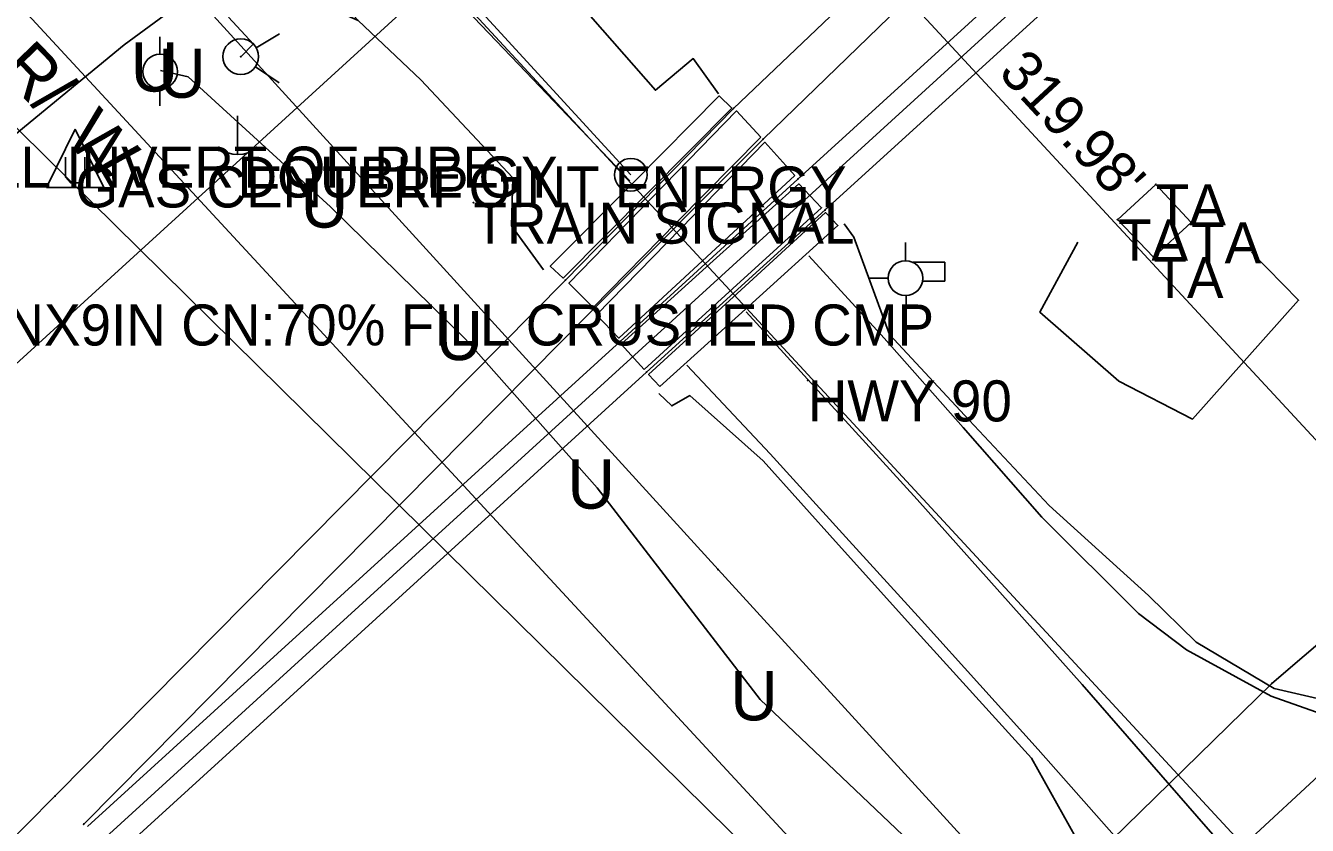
# Model space of a CAD drawing. Extents: x 1660112 to 1662239, y 668919 to 671377.
# Drawn here: x 1661444.4 to 1661600.6, y 669917.5 to 670014.9 of the extents above; entities that cross this region are included whole.
import ezdxf

# ---------------------------------------------------------------- set-up
doc = ezdxf.new("R2010")
doc.units = 0
for name, color, linetype in [('Default', 7, 'Continuous'), ('R_Annotation', 7, 'Continuous'), ('R_Horz Alg', 7, 'Continuous'), ('R_Horz Alg Annot', 7, 'Continuous'), ('S_BUILDING', 7, 'Continuous'), ('S_BUILDING_ANNOT', 7, 'Continuous'), ('S_EDGE_CONCRETE', 7, 'Continuous'), ('S_EDGE_PAVEMENT', 7, 'Continuous'), ('S_EXIST_ROW', 7, 'Continuous'), ('S_EXIST_ROW_ANNOT', 7, 'Continuous'), ('S_EXISTING_ALIGNMENT', 7, 'Continuous'), ('S_FIBER_OPTIC_CABLE', 7, 'Continuous'), ('S_MISC_STRUCTURES_ANNOT', 7, 'Continuous'), ('S_MSC_PT_SYM', 7, 'Continuous'), ('S_PAVEMENT_CROWN', 7, 'Continuous'), ('S_RAILROAD', 7, 'Continuous'), ('S_SANITARY_SEWER', 7, 'Continuous'), ('S_SHOULDER', 7, 'Continuous'), ('S_SIDE_DRAIN_ANNOT', 7, 'Continuous'), ('S_STR_PT_SYM', 7, 'Continuous'), ('S_SURVEY_TEXT_ANNOT', 7, 'Continuous'), ('S_UNDERGROUND_CABLE', 7, 'Continuous'), ('S_UTILITY_POLE', 7, 'Continuous'), ('S_UTILITY_POLE_ANNOT', 7, 'Continuous'), ('S_UTL_PT_SYM', 7, 'Continuous'), ('S_WATER_UTILITIES', 7, 'Continuous')]:
    doc.layers.add(name, color=color, linetype=linetype)

msp = doc.modelspace()

# ---------------------------------------------------------------- linework, layer by layer
at = {"layer": 'R_Horz Alg'}
msp.add_line((1661473.81, 670045.11), (1661518.2, 669996.77), dxfattribs=at)
at = {"layer": 'R_Horz Alg Annot'}
msp.add_circle((1661518.2, 669996.77), 2, dxfattribs=at)
at = {"layer": 'S_BUILDING'}
for p, q in [((1661582.19, 669995.6), (1661577.57, 669991.32)), ((1661586.47, 669990.97), (1661582.19, 669995.6)), ((1661577.5, 669991.3), (1661581.89, 669986.74)), ((1661581.89, 669986.74), (1661586.47, 669990.97))]:
    msp.add_line(p, q, dxfattribs=at)
at = {"layer": 'S_EDGE_CONCRETE'}
for points in [[(1661530.51, 670004.88), (1661528.97, 670006.37), (1661518.67, 669995.99), (1661508.37, 669985.62), (1661509.93, 669984.17), (1661520.22, 669994.53)], [(1661534.04, 670001.36), (1661523.82, 669990.98), (1661513.59, 669980.6), (1661510.64, 669983.54), (1661520.85, 669994.04), (1661531.07, 670004.54)], [(1661538.2, 669996.67), (1661527.46, 669986.77), (1661516.72, 669976.86), (1661514.03, 669979.7), (1661524.28, 669990.22), (1661534.53, 670000.74)], [(1661519.81, 669973.05), (1661517.01, 669976.14), (1661527.83, 669985.9), (1661538.65, 669995.66), (1661541.44, 669992.74), (1661530.63, 669982.89)], [(1661521.74, 669970.95), (1661520.36, 669972.41), (1661531.15, 669982.29), (1661541.93, 669992.16), (1661543.43, 669990.57), (1661532.58, 669980.76)]]:
    msp.add_lwpolyline(points, close=True, dxfattribs=at)
at = {"layer": 'S_EDGE_PAVEMENT'}
for points in [[(1661528.89, 670006.64), (1661525.81, 670010.93), (1661521.19, 670007.06), (1661512.12, 670017.42), (1661503.06, 670027.78), (1661494.14, 670038.45), (1661485.22, 670049.12), (1661475.65, 670058.13), (1661469.7, 670064.69), (1661453.26, 670082.63), (1661441.58, 670095.54), (1661429.9, 670108.45), (1661415.33, 670123.89), (1661400.76, 670139.32), (1661387.62, 670152.61), (1661374.47, 670165.9), (1661358.81, 670181.9), (1661343.14, 670197.9), (1661339.48, 670201.44), (1661329.75, 670211.05), (1661320.02, 670220.65), (1661304.77, 670236.19)], [(1661507.57, 669985.17), (1661503.63, 669990.55), (1661503.83, 669996.41), (1661492.59, 670008.33), (1661484.98, 670015.56), (1661475.91, 670025.37), (1661466.84, 670035.18), (1661454.4, 670049.73), (1661445.95, 670059), (1661437.51, 670068.28), (1661425.39, 670081.13), (1661413.28, 670093.99), (1661399.68, 670108.94), (1661386.08, 670123.89), (1661373.13, 670137.66), (1661360.18, 670151.43), (1661345.14, 670167.24), (1661330.11, 670183.04), (1661325.69, 670187.24), (1661316.74, 670196.41), (1661307.8, 670205.57), (1661291.28, 670222.16)], [(1661484.97, 670015.57), (1661481.44, 670017.1), (1661474.37, 670019.33), (1661466.03, 670019.66), (1661456.43, 670012.6), (1661444.31, 670002.59), (1661432.19, 669992.58), (1661429.76, 669993.52), (1661418.03, 669982.83), (1661399.88, 669965.82), (1661383.18, 669950.54), (1661366.48, 669935.26), (1661355.84, 669925.69), (1661345.19, 669916.12), (1661334.54, 669906.55), (1661323.9, 669896.98), (1661314.39, 669888.26), (1661304.88, 669879.54), (1661295.37, 669870.82), (1661285.87, 669862.1), (1661271.87, 669849.3), (1661257.87, 669836.51)], [(1661593.85, 669987.34), (1661599.58, 669981.47), (1661586.66, 669967), (1661577.69, 669971.61), (1661568.05, 669980.02), (1661572.66, 669988.57)], [(1661539.87, 669986.88), (1661549.09, 669976.87), (1661558.69, 669965.95), (1661568.29, 669955.03), (1661580.08, 669943.31), (1661585.93, 669938.89), (1661596.24, 669933.25), (1661605.77, 669929.84), (1661617.85, 669928.83), (1661635.53, 669933.18), (1661641.44, 669936.4), (1661650.28, 669942.7)], [(1661432.01, 669741.93), (1661449.2, 669757.82), (1661461.17, 669768.88), (1661473.15, 669779.94), (1661485.12, 669791), (1661497.09, 669802.06), (1661512.08, 669815.85), (1661527.07, 669829.65), (1661544.05, 669845.51), (1661561.04, 669861.38), (1661565.83, 669865.41), (1661573.24, 669872.37), (1661579.19, 669880.3), (1661583.76, 669891.47), (1661584.04, 669901.2), (1661578.64, 669914.49), (1661567.83, 669926.75), (1661553.64, 669942.48), (1661544.41, 669952.61), (1661535.19, 669962.75), (1661525.02, 669973.56)]]:
    msp.add_lwpolyline(points, dxfattribs=at)
at = {"layer": 'S_EXIST_ROW'}
for p, q in [((1661266.05, 669812.17), (1661715.82, 670222.22)), ((1661622.22, 669942.24), (1661404.92, 670177.11)), ((1661563.48, 669887.93), (1661347.41, 670121.48)), ((1661563.48, 669887.93), (1661622.22, 669942.24))]:
    msp.add_line(p, q, dxfattribs=at)
at = {"layer": 'S_EXISTING_ALIGNMENT'}
for p, q in [((1661299.73, 669775.22), (1661749.51, 670185.28)), ((1661613.41, 669892.86), (1661376.17, 670149.3))]:
    msp.add_line(p, q, dxfattribs=at)
at = {"layer": 'S_FIBER_OPTIC_CABLE'}
for p, q in [((1661596.3, 669934.77), (1661647.72, 669978.74)), ((1661573.33, 669912.35), (1661596.3, 669934.77))]:
    msp.add_line(p, q, dxfattribs=at)
at = {"layer": 'S_MSC_PT_SYM'}
for points in [[(1661530.69, 670004.84), (1661530.69, 670004.89), (1661530.69, 670004.84), (1661530.64, 670004.84), (1661530.69, 670004.84), (1661530.69, 670004.79), (1661530.69, 670004.84), (1661530.74, 670004.84)], [(1661534.31, 670001.1), (1661534.31, 670001.15), (1661534.31, 670001.1), (1661534.26, 670001.1), (1661534.31, 670001.1), (1661534.31, 670001.05), (1661534.31, 670001.1), (1661534.36, 670001.1)], [(1661538.56, 669996.25), (1661538.56, 669996.3), (1661538.56, 669996.25), (1661538.51, 669996.25), (1661538.56, 669996.25), (1661538.56, 669996.2), (1661538.56, 669996.25), (1661538.61, 669996.25)], [(1661499.01, 669993.37), (1661499.01, 669993.42), (1661499.01, 669993.37), (1661498.96, 669993.37), (1661499.01, 669993.37), (1661499.01, 669993.32), (1661499.01, 669993.37), (1661499.06, 669993.37)], [(1661541.88, 669992.49), (1661541.88, 669992.54), (1661541.88, 669992.49), (1661541.83, 669992.49), (1661541.88, 669992.49), (1661541.88, 669992.44), (1661541.88, 669992.49), (1661541.93, 669992.49)], [(1661510.24, 669983.94), (1661510.24, 669983.99), (1661510.24, 669983.94), (1661510.19, 669983.94), (1661510.24, 669983.94), (1661510.24, 669983.89), (1661510.24, 669983.94), (1661510.29, 669983.94)], [(1661513.66, 669980.37), (1661513.66, 669980.42), (1661513.66, 669980.37), (1661513.61, 669980.37), (1661513.66, 669980.37), (1661513.66, 669980.32), (1661513.66, 669980.37), (1661513.71, 669980.37)], [(1661516.9, 669976.45), (1661516.9, 669976.5), (1661516.9, 669976.45), (1661516.85, 669976.45), (1661516.9, 669976.45), (1661516.9, 669976.4), (1661516.9, 669976.45), (1661516.95, 669976.45)], [(1661520.12, 669972.73), (1661520.12, 669972.78), (1661520.12, 669972.73), (1661520.07, 669972.73), (1661520.12, 669972.73), (1661520.12, 669972.68), (1661520.12, 669972.73), (1661520.17, 669972.73)], [(1661539.75, 669971.71), (1661539.75, 669971.76), (1661539.75, 669971.71), (1661539.7, 669971.71), (1661539.75, 669971.71), (1661539.75, 669971.66), (1661539.75, 669971.71), (1661539.8, 669971.71)], [(1661448.04, 669921.07), (1661448.04, 669921.12), (1661448.04, 669921.07), (1661447.98, 669921.07), (1661448.04, 669921.07), (1661448.04, 669921.02), (1661448.04, 669921.07), (1661448.08, 669921.07)], [(1661451.52, 669917.63), (1661451.52, 669917.68), (1661451.52, 669917.63), (1661451.47, 669917.63), (1661451.52, 669917.63), (1661451.52, 669917.58), (1661451.52, 669917.63), (1661451.57, 669917.63)]]:
    msp.add_lwpolyline(points, dxfattribs=at)
at = {"layer": 'S_PAVEMENT_CROWN'}
for points in [[(1661518.06, 669996.03), (1661505.4, 670009.31), (1661492.74, 670022.59), (1661480.19, 670036.99), (1661467.64, 670051.39), (1661473.76, 670044.39), (1661461.34, 670057.98), (1661445.4, 670075.38), (1661443.99, 670076.39), (1661432.69, 670088.65), (1661421.39, 670100.9), (1661407.48, 670115.88), (1661393.57, 670130.85), (1661380.41, 670144.59), (1661367.25, 670158.33), (1661351.88, 670174.26), (1661336.51, 670190.18), (1661332.38, 670194.36), (1661323.21, 670203.51), (1661314.05, 670212.66), (1661297.56, 670228.68)], [(1661532.25, 669980.05), (1661542.23, 669969.08), (1661553.09, 669957.19), (1661563.16, 669945.92), (1661573.22, 669934.64), (1661588.29, 669917.36), (1661603.37, 669900.08)]]:
    msp.add_lwpolyline(points, dxfattribs=at)
at = {"layer": 'S_RAILROAD'}
for p, q in [((1661530.69, 670004.84), (1661583.12, 670054.69)), ((1661534.31, 670001.1), (1661586.39, 670051.53)), ((1661538.56, 669996.25), (1661592.63, 670045.46)), ((1661541.88, 669992.49), (1661596.12, 670041.9)), ((1661510.24, 669983.94), (1661530.69, 670004.84)), ((1661513.66, 669980.37), (1661534.31, 670001.1)), ((1661516.9, 669976.45), (1661538.56, 669996.25)), ((1661520.12, 669972.73), (1661541.88, 669992.49)), ((1661551.67, 669986.28), (1661551.67, 669988.53)), ((1661556.48, 669986.13), (1661552.6, 669986.13)), ((1661556.48, 669983.8), (1661556.48, 669986.13)), ((1661448.04, 669921.07), (1661510.24, 669983.94)), ((1661549.58, 669984.15), (1661547.25, 669984.15)), ((1661556.48, 669983.8), (1661553.76, 669983.8)), ((1661551.75, 669979.74), (1661551.75, 669982.06)), ((1661451.52, 669917.63), (1661513.66, 669980.37)), ((1661451.97, 669917.34), (1661516.9, 669976.45)), ((1661455.22, 669913.63), (1661520.12, 669972.73)), ((1661397.52, 669870.6), (1661448.04, 669921.07))]:
    msp.add_line(p, q, dxfattribs=at)
msp.add_circle((1661551.67, 669984.17), 2.13, dxfattribs=at)
at = {"layer": 'S_SANITARY_SEWER'}
msp.add_line((1661704.02, 669745.54), (1661292.91, 670150.69), dxfattribs=at)
at = {"layer": 'S_SHOULDER'}
for points in [[(1661544.18, 669990.78), (1661545.38, 669989.16), (1661549.73, 669977.29), (1661559.45, 669966.88), (1661569.17, 669956.48), (1661581.29, 669945.51), (1661587.1, 669939.82), (1661596.61, 669934.16), (1661606.09, 669931.97), (1661618.1, 669932.69), (1661634.83, 669936.71), (1661634.11, 669936.74), (1661641.01, 669939.29), (1661649.51, 669944.11), (1661652.54, 669946.88), (1661670.8, 669962.78), (1661689.06, 669978.67)], [(1661565.9, 669865.41), (1661571.88, 669873.46), (1661576.91, 669881.7), (1661580, 669892.53), (1661579.44, 669899.68), (1661574.75, 669911.86), (1661567.03, 669925.66), (1661552.68, 669941.47), (1661543.51, 669951.68), (1661534.34, 669961.89), (1661525.37, 669969.85), (1661523.19, 669968.6), (1661521.62, 669970.1)]]:
    msp.add_lwpolyline(points, dxfattribs=at)
at = {"layer": 'S_STR_PT_SYM'}
for points in [[(1661582.19, 669995.6), (1661582.19, 669995.65), (1661582.19, 669995.6), (1661582.14, 669995.6), (1661582.19, 669995.6), (1661582.19, 669995.55), (1661582.19, 669995.6), (1661582.24, 669995.6)], [(1661577.5, 669991.3), (1661577.5, 669991.35), (1661577.5, 669991.3), (1661577.45, 669991.3), (1661577.5, 669991.3), (1661577.5, 669991.25), (1661577.5, 669991.3), (1661577.55, 669991.3)], [(1661577.57, 669991.32), (1661577.57, 669991.37), (1661577.57, 669991.32), (1661577.52, 669991.32), (1661577.57, 669991.32), (1661577.57, 669991.27), (1661577.57, 669991.32), (1661577.62, 669991.32)], [(1661586.47, 669990.97), (1661586.47, 669991.02), (1661586.47, 669990.97), (1661586.42, 669990.97), (1661586.47, 669990.97), (1661586.47, 669990.92), (1661586.47, 669990.97), (1661586.52, 669990.97)], [(1661581.89, 669986.74), (1661581.89, 669986.79), (1661581.89, 669986.74), (1661581.84, 669986.74), (1661581.89, 669986.74), (1661581.89, 669986.69), (1661581.89, 669986.74), (1661581.94, 669986.74)]]:
    msp.add_lwpolyline(points, dxfattribs=at)
at = {"layer": 'S_UNDERGROUND_CABLE'}
for p, q in [((1661464.23, 670008.69), (1661460.87, 670009.46)), ((1661481.59, 669992.88), (1661464.23, 670008.69)), ((1661450.49, 670002.31), (1661446.96, 669995.22)), ((1661450.49, 670002.31), (1661453.97, 669995.22)), ((1661449.29, 669996.46), (1661449.29, 669998.9)), ((1661451.65, 669998.9), (1661451.65, 669996.46)), ((1661449.91, 669995.8), (1661449.29, 669996.46)), ((1661451.65, 669996.46), (1661451.11, 669995.8)), ((1661446.96, 669995.22), (1661453.97, 669995.22)), ((1661451.11, 669995.8), (1661449.91, 669995.8)), ((1661498.03, 669976.72), (1661481.59, 669992.88)), ((1661514.09, 669958.62), (1661498.03, 669976.72)), ((1661533.95, 669932.83), (1661514.09, 669958.62)), ((1661556.51, 669911.39), (1661533.95, 669932.83))]:
    msp.add_line(p, q, dxfattribs=at)
at = {"layer": 'S_UTILITY_POLE'}
for p, q in [((1661460.79, 670011.43), (1661460.79, 670013.56)), ((1661460.79, 670007.21), (1661460.79, 670005.16)), ((1661470.24, 670003.94), (1661470.24, 669999.21))]:
    msp.add_line(p, q, dxfattribs=at)
msp.add_circle((1661460.82, 670009.35), 2.11, dxfattribs=at)
msp.add_arc((1661470.31, 670002.63), 3.41, 226.3972, 313.6028, dxfattribs=at)
at = {"layer": 'S_UTL_PT_SYM'}
for points in [[(1661472.19, 670012.72), (1661472.19, 670012.77), (1661472.19, 670012.72), (1661472.14, 670012.72), (1661472.19, 670012.72), (1661472.19, 670012.67), (1661472.19, 670012.72), (1661472.24, 670012.72)], [(1661472.2, 670012.7), (1661472.2, 670012.75), (1661472.2, 670012.7), (1661472.15, 670012.7), (1661472.2, 670012.7), (1661472.2, 670012.65), (1661472.2, 670012.7), (1661472.25, 670012.7)], [(1661470.66, 670011.15), (1661470.66, 670011.2), (1661470.66, 670011.15), (1661470.61, 670011.15), (1661470.66, 670011.15), (1661470.66, 670011.1), (1661470.66, 670011.15), (1661470.71, 670011.15)], [(1661528.82, 669948.66), (1661528.82, 669948.71), (1661528.82, 669948.66), (1661528.77, 669948.66), (1661528.82, 669948.66), (1661528.82, 669948.61), (1661528.82, 669948.66), (1661528.87, 669948.66)], [(1661596.3, 669934.77), (1661596.3, 669934.82), (1661596.3, 669934.77), (1661596.25, 669934.77), (1661596.3, 669934.77), (1661596.3, 669934.72), (1661596.3, 669934.77), (1661596.35, 669934.77)]]:
    msp.add_lwpolyline(points, dxfattribs=at)
at = {"layer": 'S_WATER_UTILITIES'}
for p, q in [((1661528.82, 669948.66), (1661452.55, 670032.39)), ((1661472.2, 670012.7), (1661469.14, 670015.98)), ((1661472.55, 670012.22), (1661475.37, 670013.95)), ((1661472.19, 670012.72), (1661470.66, 670011.15)), ((1661472.43, 670009.91), (1661475.34, 670007.98)), ((1661569.45, 669904.22), (1661528.82, 669948.66))]:
    msp.add_line(p, q, dxfattribs=at)
msp.add_circle((1661470.65, 670011.16), 2.18, dxfattribs=at)

# ---------------------------------------------------------------- texts
at = {"layer": 'Default'}
for p in [(1661457.24, 670006.91), (1661460.6, 670006.15), (1661477.96, 669990.33), (1661494.4, 669974.18), (1661510.46, 669956.08), (1661530.32, 669930.28)]:
    msp.add_text('U', height=6, rotation=360, dxfattribs=at).set_placement(p)
at = {"layer": 'R_Annotation'}
for s, p in [('R', (1661441.03, 670009.39)), ('/', (1661444.96, 670005.32)), ('W', (1661449.03, 670001.1))]:
    msp.add_text(s, height=6, rotation=313.9993, dxfattribs=at).set_placement(p)
at = {"layer": 'S_BUILDING_ANNOT'}
for p in [(1661582.19, 669990.6), (1661577.57, 669986.32), (1661586.47, 669985.97), (1661581.89, 669981.74)]:
    msp.add_text('TA', height=5, dxfattribs=at).set_placement(p)
at = {"layer": 'S_EXIST_ROW_ANNOT'}
msp.add_text("319.98'", height=5, rotation=312.7737, dxfattribs=at).set_placement((1661562.86, 670009.08))
at = {"layer": 'S_MISC_STRUCTURES_ANNOT'}
msp.add_text('TRAIN SIGNAL', height=5, dxfattribs=at).set_placement((1661499.01, 669988.37))
at = {"layer": 'S_SIDE_DRAIN_ANNOT'}
for s, p in [('CN:70% FILL INVERT OF PIPE', (1661407.39, 669995.2)), ('DI:20INX9IN CN:70% FILL CRUSHED CMP', (1661424, 669975.96))]:
    msp.add_text(s, height=5, dxfattribs=at).set_placement(p)
at = {"layer": 'S_SURVEY_TEXT_ANNOT'}
msp.add_text('HWY 90', height=5, dxfattribs=at).set_placement((1661539.75, 669966.71))
at = {"layer": 'S_UTILITY_POLE_ANNOT'}
for s, p in [('DOUBLE GY', (1661470.26, 669993.99)), ('GAS CENTERPOINT ENERGY', (1661450.49, 669992.78))]:
    msp.add_text(s, height=5, dxfattribs=at).set_placement(p)

doc.saveas('drawing.dxf')
